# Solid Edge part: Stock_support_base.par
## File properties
Title: Stock Support Base
Author: Abhinav Rai
Template: Normal.par
Last saved by: SOFT
Revision: 28
Application: Solid Edge
Accuracy: 0.99
Material: aluminum
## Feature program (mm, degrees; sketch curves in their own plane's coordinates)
sketch for "unnamed RevolvedProtrusion 1" plane through (0, 0, 0) normal (0, -1, 0) x-axis (1, 0, 0)
  line (0, 29.2468) -> (71.7103, 29.2468)
  line (71.7103, 29.2468) -> (71.7103, 19.7218)
  line (71.7103, 19.7218) -> (165.1, -256.5032)
  line (165.1, -256.5032) -> (215.9, -256.5032)
  line (215.9, -256.5032) -> (215.9, -281.9032)
  line (215.9, -281.9032) -> (156.9298, -281.9032)
  line (156.9298, -281.9032) -> (85.052, -69.3053)
  arc centre (73.021, -73.3729) radius 12.7 from (60.325, -73.0538) to (85.052, -69.3053) cw
  line (60.325, -73.0538) -> (57.15, -199.3532)
  line (57.15, -199.3532) -> (0, -199.3532)
  line (0, 29.2468) -> (0, -199.3532)
revolve "unnamed RevolvedProtrusion 1" add full turn 360 deg
sketch for "unnamed Hole 1" plane through (0, 0, 29.2468) normal (0, 0, 1) x-axis (1, 0, 0)
  hole centre (0, 0) bore radius 38.1
hole "unnamed Hole 1" through
sketch for "ExtrudedProtrusion_2" plane through (0, 0, -256.5032) normal (0, 0, 1) x-axis (0, 1, 0)
  arc centre (0, -119.2664) radius 41.0756 from (-18.7686, -155.8034) to (18.7686, -155.8034) ccw
  line (-18.7686, -197.1314) -> (-18.7686, -155.8034)
  arc centre (0, -197.1314) radius 18.7686 from (18.7686, -197.1314) to (-18.7686, -197.1314) cw
  line (18.7686, -197.1314) -> (18.7686, -155.8034)
extrude "ExtrudedProtrusion_2" add finite 12.7 along +normal
sketch for "unnamed Hole 2" plane through (187.8036, 0, -243.8032) normal (0, 0, 1) x-axis (1, 0, 0)
hole "unnamed Hole 2" through
fillet "Round_4" radius 3.175
pattern "unnamed Pattern 1" of "ExtrudedProtrusion_2", "unnamed Hole 2", "Round_4"
pattern "unnamed Pattern 2"
sketch for "ExtrudedProtrusion_3" plane through (0, -134.62, 0) normal (0, -1, 0) x-axis (1, 0, 0)
  circle centre (0, -2.5032) radius 19.05
extrude "ExtrudedProtrusion_3" add  Plane_Distance = 134.62 mm
adv blend "unnamed AdvBlend 1"
sketch for "ExtrudedProtrusion_4" plane through (0, -134.62, -2.5032) normal (0, -1, 0) x-axis (1, 0, 0)
  circle centre (0, -3.81) radius 22.225
extrude "ExtrudedProtrusion_4" add finite 9.525 along +normal
mirror "unnamed Mirror 1" of "ExtrudedProtrusion_4", "unnamed AdvBlend 1", "ExtrudedProtrusion_3" about plane through (0, 0, 0) normal (0, -1, 0)
extrude "unnamed Protrusion 1" add
adv blend "unnamed AdvBlend 2"
extrude "unnamed Protrusion 2" add finite 9.525
sketch for "ExtrudedProtrusion_7" plane through (104.775, 0, 0) normal (1, 0, 0) x-axis (0, 1, 0)
  circle centre (0, -167.6032) radius 19.05
extrude "ExtrudedProtrusion_7" add finite 41.275 along +normal  Plane_Distance = 104.775 mm
sketch for "unnamed Hole 3" plane through (146.05, 0, -167.6032) normal (1, 0, 0) x-axis (0, 1, 0)
  hole centre (0, 0) bore radius 7.9375
hole "unnamed Hole 3" through
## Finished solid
Body 1: solid body, 54 faces, 95 edges, 41 vertices.
  Faces by surface: plane 26, cylinder 19, torus 4, cone 3, blend 2
  Edges by curve: circle 57, intersection 20, line 18
Bounding box of the edges (mm; curved faces can reach further): 431.800 x 431.800 x 311.150, from (-215.9, -215.9, -281.9032) to (215.9, 215.9, 29.2468).
Cylindrical faces by radius (mm): R7.9375 x1, R11.1125 x3, R15.875 x3, R18.7686 x3, R19.05 x4, R22.225 x2, R38.1 x1, R71.7103 x1, R215.9 x1
Conical faces (half-angle, radius in mm at the cone's reference point): 1.44 deg R60.325 x1, 18.68 deg R71.7103 x1, 18.68 deg R156.9298 x1
Toroidal faces (ring radius, tube radius in mm): R73.021 r12.7 x1, R163.0843 r3.175 x3
Planar faces by outward normal: +x 1, +y 4, +z 10, -x 1, -y 4, -z 2, oblique 4
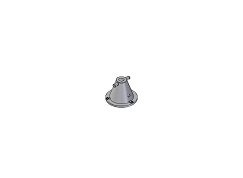
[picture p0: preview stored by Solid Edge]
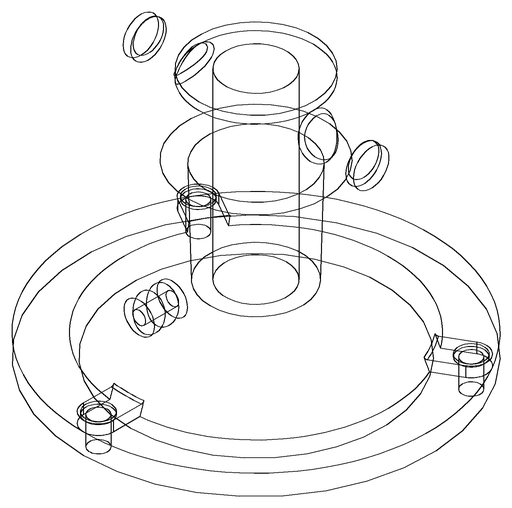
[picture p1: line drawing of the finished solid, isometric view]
